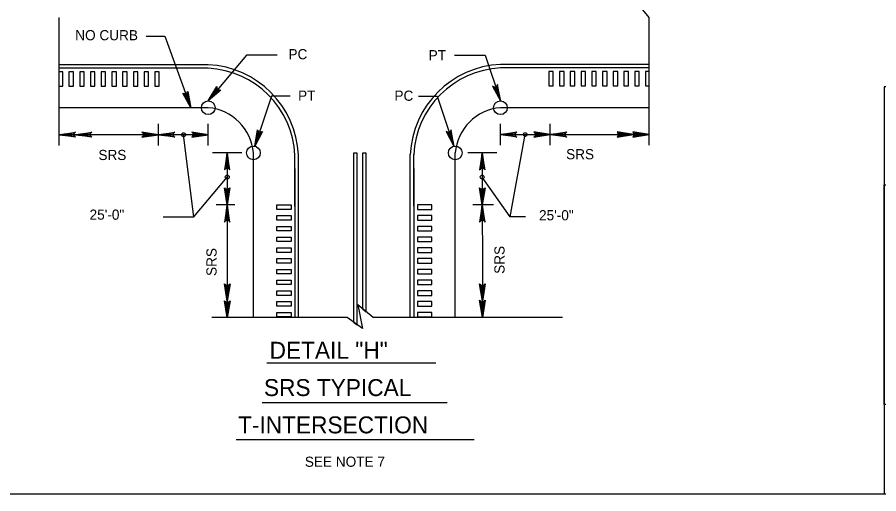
# Model space of a CAD drawing. Extents: x 632008 to 634206, y 294231 to 297795.
# Drawn here: x 632378.2 to 632632.3, y 296621.6 to 296762.1 of the extents above; entities that cross this region are included whole.
import ezdxf

# ---------------------------------------------------------------- set-up
doc = ezdxf.new("R2010")
doc.units = 0
for name, color, linetype in [('1', 7, 'Continuous'), ('3', 7, 'Continuous'), ('Level 2', 7, 'Continuous')]:
    doc.layers.add(name, color=color, linetype=linetype)

msp = doc.modelspace()

# ---------------------------------------------------------------- linework, layer by layer
at = {"layer": '1'}
for p, q in [((632451.78, 296660.25), (632501.65, 296660.25)), ((632450.44, 296648.57), (632504.99, 296648.57)), ((632442.7, 296637.57), (632512.92, 296637.57))]:
    msp.add_line(p, q, dxfattribs=at)
msp.add_lwpolyline([(632833.86, 296621.62), (632833.86, 297185.62), (632047.86, 297185.62), (632047.86, 296621.62), (632833.86, 296621.62), (632833.86, 296647.98), (632633.86, 296647.98), (632633.86, 296712.66), (632833.86, 296712.66), (632833.86, 296741.62), (632633.86, 296741.62), (632633.86, 296621.62), (632712.66, 296621.62), (632712.66, 296647.98), (632712.66, 296621.62), (632789.66, 296621.62), (632789.66, 296647.98), (632789.66, 296635.66), (632833.86, 296635.66)], dxfattribs=at)
for points in [[(632478.41, 296671.46), (632478.41, 296722.02), (632477.36, 296722.02), (632477.36, 296672.24)], [(632481.05, 296675.29), (632481.05, 296722.02), (632480, 296722.02), (632480, 296676.15)]]:
    msp.add_lwpolyline(points, close=True, dxfattribs=at)
at = {"layer": '3'}
for points in [[(632458.65, 296738.86), (632453.18, 296738.86), (632448.22, 296724.09)], [(632496.54, 296738.86), (632502, 296738.86), (632506.97, 296724.09)], [(632450.23, 296728.27), (632449.86, 296728.21), (632448.22, 296724.09), (632450.23, 296728.27), (632450.5, 296728.43), (632448.22, 296724.09), (632449.42, 296728.36), (632449.16, 296728.61), (632448.22, 296724.09), (632449.03, 296728.92), (632449.16, 296728.61)], [(632504.95, 296728.27), (632505.32, 296728.21), (632506.97, 296724.09), (632504.95, 296728.27), (632504.69, 296728.43), (632506.97, 296724.09), (632505.76, 296728.36), (632506.02, 296728.61), (632506.97, 296724.09), (632506.15, 296728.92), (632506.02, 296728.61)]]:
    msp.add_lwpolyline(points, dxfattribs=at)
for centre in [(632447.83, 296722.1), (632507.36, 296722.1)]:
    msp.add_circle(centre, 2.03, dxfattribs=at)
at = {"layer": 'Level 2'}
for p, q in [((632564.54, 296762.01), (632561.33, 296765.96)), ((632390.51, 296724.3), (632390.51, 296762.01)), ((632564.54, 296724.34), (632564.54, 296762.01)), ((632434.51, 296748.07), (632390.51, 296748.07)), ((632564.54, 296748.16), (632520.69, 296748.16)), ((632564.54, 296747.15), (632520.69, 296747.15)), ((632434.51, 296747.05), (632390.51, 296747.05)), ((632434.51, 296735.42), (632390.65, 296735.42)), ((632564.54, 296735.42), (632520.67, 296735.42)), ((632419.79, 296724.3), (632419.79, 296730.65)), ((632434.51, 296724.3), (632434.51, 296730.65)), ((632520.67, 296724.34), (632520.67, 296730.69)), ((632535.4, 296724.34), (632535.4, 296730.69)), ((632434.51, 296727.47), (632390.51, 296727.47)), ((632520.67, 296727.51), (632564.54, 296727.51)), ((632444.41, 296722.1), (632435.81, 296722.1)), ((632440.11, 296722.1), (632440.11, 296673.62)), ((632447.83, 296673.62), (632447.83, 296722.1)), ((632507.36, 296673.62), (632507.36, 296722.1)), ((632519.66, 296722.1), (632511.05, 296722.1)), ((632515.35, 296722.1), (632515.36, 296673.62)), ((632460.03, 296706.43), (632460.03, 296721.49)), ((632461.09, 296673.62), (632461.09, 296721.59)), ((632461.09, 296706.43), (632461.09, 296721.49)), ((632494.11, 296673.62), (632494.11, 296721.59)), ((632495.17, 296706.43), (632495.17, 296721.59)), ((632460.03, 296717.47), (632460.03, 296673.62)), ((632495.17, 296717.47), (632495.17, 296673.62)), ((632442.36, 296706.76), (632436.81, 296706.76)), ((632518.66, 296706.76), (632512.59, 296706.76)), ((632483.11, 296673.62), (632478.61, 296677.27)), ((632478.61, 296677.27), (632479.96, 296670.3)), ((632475.53, 296673.62), (632435.58, 296673.62)), ((632479.96, 296670.3), (632475.53, 296673.62)), ((632520.99, 296673.62), (632483.11, 296673.62)), ((632539.02, 296673.62), (632495.17, 296673.62))]:
    msp.add_line(p, q, dxfattribs=at)
for points in [[(632416.18, 296756.53), (632421.7, 296756.53), (632429.38, 296735.42)], [(632454.88, 296750.9), (632445.84, 296750.9), (632434.51, 296737.44)], [(632507.13, 296750.86), (632516.16, 296750.86), (632520.67, 296737.44)], [(632390.51, 296741.76), (632391.57, 296741.76), (632391.57, 296745.98), (632390.51, 296745.98)], [(632564.54, 296746.07), (632563.48, 296746.07), (632563.48, 296741.85), (632564.54, 296741.85)], [(632518.66, 296741.62), (632519.03, 296741.57), (632520.67, 296737.44), (632518.66, 296741.62), (632518.39, 296741.78), (632520.67, 296737.44), (632519.47, 296741.71), (632519.73, 296741.97), (632520.67, 296737.44), (632519.86, 296742.27), (632519.73, 296741.97)], [(632428.34, 296739.94), (632428.09, 296739.67), (632429.38, 296735.42), (632428.34, 296739.94), (632428.45, 296740.23), (632429.38, 296735.42), (632427.66, 296739.5), (632427.29, 296739.54), (632429.38, 296735.42), (632427, 296739.7), (632427.29, 296739.54)], [(632437.93, 296740.58), (632437.56, 296740.67), (632434.51, 296737.44), (632437.93, 296740.58), (632438.23, 296740.63), (632434.51, 296737.44), (632437.2, 296740.96), (632437.06, 296741.3), (632434.51, 296737.44), (632437.05, 296741.63), (632437.06, 296741.3)], [(632395.11, 296726.9), (632394.95, 296727.23), (632390.51, 296727.47), (632395.11, 296726.9), (632395.35, 296726.69), (632390.51, 296727.47), (632394.94, 296727.69), (632395.1, 296728.02), (632390.51, 296727.47), (632395.35, 296728.24), (632395.1, 296728.02)], [(632399.93, 296726.9), (632399.77, 296727.23), (632395.33, 296727.47), (632399.93, 296726.9), (632400.17, 296726.69), (632395.33, 296727.47), (632399.76, 296727.69), (632399.92, 296728.02), (632395.33, 296727.47), (632400.17, 296728.24), (632399.92, 296728.02)], [(632415.19, 296726.9), (632415.35, 296727.23), (632419.79, 296727.47), (632415.19, 296726.9), (632414.95, 296726.69), (632419.79, 296727.47), (632415.36, 296727.69), (632415.2, 296728.02), (632419.79, 296727.47), (632414.95, 296728.24), (632415.2, 296728.02)], [(632424.39, 296726.9), (632424.22, 296727.23), (632419.79, 296727.47), (632424.39, 296726.9), (632424.63, 296726.69), (632419.79, 296727.47), (632424.22, 296727.69), (632424.38, 296728.02), (632419.79, 296727.47), (632424.63, 296728.24), (632424.38, 296728.02)], [(632421.26, 296703.28), (632430.3, 296703.28), (632427.24, 296727.47)], [(632429.91, 296726.9), (632430.08, 296727.23), (632434.51, 296727.47), (632429.91, 296726.9), (632429.67, 296726.69), (632434.51, 296727.47), (632430.08, 296727.69), (632429.92, 296728.02), (632434.51, 296727.47), (632429.67, 296728.24), (632429.92, 296728.02)], [(632525.27, 296726.94), (632525.11, 296727.27), (632520.67, 296727.51), (632525.27, 296726.94), (632525.51, 296726.73), (632520.67, 296727.51), (632525.1, 296727.73), (632525.26, 296728.06), (632520.67, 296727.51), (632525.51, 296728.28), (632525.26, 296728.06)], [(632528.12, 296703.28), (632523.52, 296703.28), (632528.01, 296727.5)], [(632530.8, 296726.94), (632530.96, 296727.27), (632535.4, 296727.51), (632530.8, 296726.94), (632530.56, 296726.73), (632535.4, 296727.51), (632530.97, 296727.73), (632530.81, 296728.06), (632535.4, 296727.51), (632530.56, 296728.28), (632530.81, 296728.06)], [(632540, 296726.94), (632539.83, 296727.27), (632535.4, 296727.51), (632540, 296726.94), (632540.24, 296726.73), (632535.4, 296727.51), (632539.83, 296727.73), (632539.99, 296728.06), (632535.4, 296727.51), (632540.24, 296728.28), (632539.99, 296728.06)], [(632555.33, 296726.94), (632555.5, 296727.27), (632559.93, 296727.51), (632555.33, 296726.94), (632555.09, 296726.73), (632559.93, 296727.51), (632555.5, 296727.73), (632555.34, 296728.06), (632559.93, 296727.51), (632555.09, 296728.28), (632555.34, 296728.06)], [(632559.94, 296726.94), (632560.11, 296727.27), (632564.55, 296727.51), (632559.94, 296726.94), (632559.71, 296726.73), (632564.55, 296727.51), (632560.12, 296727.73), (632559.96, 296728.06), (632564.55, 296727.51), (632559.71, 296728.28), (632559.96, 296728.06)], [(632440.71, 296717.31), (632440.37, 296717.48), (632440.11, 296722.1), (632440.71, 296717.31), (632440.92, 296717.06), (632440.11, 296722.1), (632439.88, 296717.49), (632439.54, 296717.32), (632440.11, 296722.1), (632439.31, 296717.06), (632439.54, 296717.32)], [(632515.96, 296717.31), (632515.61, 296717.48), (632515.35, 296722.1), (632515.96, 296717.31), (632516.16, 296717.06), (632515.35, 296722.1), (632515.12, 296717.49), (632514.78, 296717.32), (632515.35, 296722.1), (632514.55, 296717.06), (632514.78, 296717.32)], [(632421.26, 296703.28), (632430.3, 296703.28), (632440.13, 296714.93)], [(632528.12, 296703.28), (632523.52, 296703.28), (632515.31, 296714.93)], [(632440.71, 296711.56), (632440.37, 296711.38), (632440.11, 296706.76), (632440.71, 296711.56), (632440.92, 296711.8), (632440.11, 296706.76), (632439.88, 296711.37), (632439.54, 296711.54), (632440.11, 296706.76), (632439.31, 296711.8), (632439.54, 296711.54)], [(632515.96, 296711.56), (632515.61, 296711.38), (632515.35, 296706.76), (632515.96, 296711.56), (632516.16, 296711.8), (632515.35, 296706.76), (632515.12, 296711.37), (632514.78, 296711.54), (632515.35, 296706.76), (632514.55, 296711.8), (632514.78, 296711.54)], [(632440.71, 296701.97), (632440.37, 296702.14), (632440.11, 296706.76), (632440.71, 296701.97), (632440.92, 296701.72), (632440.11, 296706.76), (632439.88, 296702.15), (632439.54, 296701.98), (632440.11, 296706.76), (632439.31, 296701.72), (632439.54, 296701.98)], [(632515.96, 296701.97), (632515.61, 296702.14), (632515.35, 296706.76), (632515.96, 296701.97), (632516.16, 296701.72), (632515.35, 296706.76), (632515.12, 296702.15), (632514.78, 296701.98), (632515.35, 296706.76), (632514.55, 296701.72), (632514.78, 296701.98)], [(632440.72, 296683.22), (632440.37, 296683.05), (632440.12, 296678.43), (632440.72, 296683.22), (632440.93, 296683.47), (632440.12, 296678.43), (632439.89, 296683.04), (632439.55, 296683.21), (632440.12, 296678.43), (632439.32, 296683.47), (632439.55, 296683.21)], [(632515.96, 296683.22), (632515.61, 296683.05), (632515.36, 296678.43), (632515.96, 296683.22), (632516.17, 296683.47), (632515.36, 296678.43), (632515.13, 296683.04), (632514.79, 296683.21), (632515.36, 296678.43), (632514.56, 296683.47), (632514.79, 296683.21)], [(632515.96, 296678.42), (632515.61, 296678.24), (632515.36, 296673.62), (632515.96, 296678.42), (632516.17, 296678.66), (632515.36, 296673.62), (632515.13, 296678.23), (632514.79, 296678.4), (632515.36, 296673.62), (632514.56, 296678.66), (632514.79, 296678.4)], [(632440.72, 296678.21), (632440.37, 296678.05), (632440.12, 296673.62), (632440.72, 296678.21), (632440.93, 296678.45), (632440.12, 296673.62), (632439.89, 296678.04), (632439.55, 296678.2), (632440.12, 296673.62), (632439.32, 296678.45), (632439.55, 296678.2)]]:
    msp.add_lwpolyline(points, dxfattribs=at)
for points in [[(632393.42, 296741.76), (632394.74, 296741.76), (632394.74, 296745.98), (632393.42, 296745.98)], [(632396.59, 296741.76), (632397.91, 296741.76), (632397.91, 296745.98), (632396.59, 296745.98)], [(632399.75, 296741.76), (632401.07, 296741.76), (632401.07, 296745.98), (632399.75, 296745.98)], [(632402.92, 296741.76), (632404.24, 296741.76), (632404.24, 296745.98), (632402.92, 296745.98)], [(632406.09, 296741.76), (632407.41, 296741.76), (632407.41, 296745.98), (632406.09, 296745.98)], [(632409.25, 296741.76), (632410.57, 296741.76), (632410.57, 296745.98), (632409.25, 296745.98)], [(632412.42, 296741.76), (632413.74, 296741.76), (632413.74, 296745.98), (632412.42, 296745.98)], [(632415.59, 296741.76), (632416.91, 296741.76), (632416.91, 296745.98), (632415.59, 296745.98)], [(632418.75, 296741.76), (632420.07, 296741.76), (632420.07, 296745.98), (632418.75, 296745.98)], [(632534.97, 296741.85), (632536.29, 296741.85), (632536.29, 296746.07), (632534.97, 296746.07)], [(632538.14, 296741.85), (632539.46, 296741.85), (632539.46, 296746.07), (632538.14, 296746.07)], [(632541.31, 296741.85), (632542.63, 296741.85), (632542.63, 296746.07), (632541.31, 296746.07)], [(632544.48, 296741.85), (632545.8, 296741.85), (632545.8, 296746.07), (632544.48, 296746.07)], [(632547.64, 296741.85), (632548.96, 296741.85), (632548.96, 296746.07), (632547.64, 296746.07)], [(632550.81, 296741.85), (632552.13, 296741.85), (632552.13, 296746.07), (632550.81, 296746.07)], [(632553.98, 296741.85), (632555.3, 296741.85), (632555.3, 296746.07), (632553.98, 296746.07)], [(632557.14, 296741.85), (632558.46, 296741.85), (632558.46, 296746.07), (632557.14, 296746.07)], [(632560.31, 296741.85), (632561.63, 296741.85), (632561.63, 296746.07), (632560.31, 296746.07)], [(632454.74, 296705.44), (632454.74, 296706.76), (632458.96, 296706.76), (632458.96, 296705.44)], [(632500.46, 296705.44), (632500.46, 296706.76), (632496.24, 296706.76), (632496.24, 296705.44)], [(632454.74, 296702.28), (632454.74, 296703.6), (632458.96, 296703.6), (632458.96, 296702.28)], [(632500.46, 296702.28), (632500.46, 296703.6), (632496.24, 296703.6), (632496.24, 296702.28)], [(632454.74, 296699.11), (632454.74, 296700.43), (632458.96, 296700.43), (632458.96, 296699.11)], [(632500.46, 296699.11), (632500.46, 296700.43), (632496.24, 296700.43), (632496.24, 296699.11)], [(632454.74, 296695.94), (632454.74, 296697.26), (632458.96, 296697.26), (632458.96, 296695.94)], [(632500.46, 296695.94), (632500.46, 296697.26), (632496.24, 296697.26), (632496.24, 296695.94)], [(632454.74, 296692.77), (632454.74, 296694.09), (632458.96, 296694.09), (632458.96, 296692.77)], [(632500.46, 296692.77), (632500.46, 296694.09), (632496.24, 296694.09), (632496.24, 296692.77)], [(632454.74, 296689.61), (632454.74, 296690.93), (632458.96, 296690.93), (632458.96, 296689.61)], [(632500.46, 296689.61), (632500.46, 296690.93), (632496.24, 296690.93), (632496.24, 296689.61)], [(632454.74, 296686.44), (632454.74, 296687.76), (632458.96, 296687.76), (632458.96, 296686.44)], [(632500.46, 296686.44), (632500.46, 296687.76), (632496.24, 296687.76), (632496.24, 296686.44)], [(632454.74, 296683.27), (632454.74, 296684.59), (632458.96, 296684.59), (632458.96, 296683.27)], [(632500.46, 296683.27), (632500.46, 296684.59), (632496.24, 296684.59), (632496.24, 296683.27)], [(632454.74, 296680.11), (632454.74, 296681.43), (632458.96, 296681.43), (632458.96, 296680.11)], [(632500.46, 296680.11), (632500.46, 296681.43), (632496.24, 296681.43), (632496.24, 296680.11)], [(632454.74, 296676.94), (632454.74, 296678.26), (632458.96, 296678.26), (632458.96, 296676.94)], [(632500.46, 296676.94), (632500.46, 296678.26), (632496.24, 296678.26), (632496.24, 296676.94)], [(632454.74, 296673.77), (632454.74, 296675.09), (632458.96, 296675.09), (632458.96, 296673.77)], [(632500.46, 296673.77), (632500.46, 296675.09), (632496.24, 296675.09), (632496.24, 296673.77)]]:
    msp.add_lwpolyline(points, close=True, dxfattribs=at)
for centre, radius in [((632434.51, 296735.42), 2.03), ((632520.67, 296735.42), 2.03), ((632427.24, 296727.47), 0.558), ((632528.01, 296727.5), 0.558), ((632440.12, 296714.97), 0.581), ((632515.3, 296714.97), 0.581)]:
    msp.add_circle(centre, radius, dxfattribs=at)
for centre, radius, start, end in [((632433.23, 296720.21), 27.91, 2.6354, 87.3646), ((632521.97, 296720.3), 27.91, 92.6354, 177.3646), ((632521.97, 296720.3), 26.86, 92.6354, 177.3646), ((632433.23, 296720.21), 26.86, 2.6354, 87.3646), ((632433.28, 296720.87), 14.6, 4.837, 85.163), ((632521.9, 296720.87), 14.6, 94.837, 175.163)]:
    msp.add_arc(centre, radius, start, end, dxfattribs=at)

# ---------------------------------------------------------------- texts
at = {"layer": '3'}
for s, p in [('PT', (632461.01, 296737.46)), ('PC', (632489.43, 296737.46))]:
    msp.add_text(s, height=3, dxfattribs=at).set_placement(p)
at = {"layer": 'Level 2'}
for s, height, p in [('NO CURB', 3, (632395.28, 296755.3)), ('PC', 3, (632458.17, 296749.7)), ('PT', 3, (632499.52, 296749.4)), ('SRS', 3, (632402.11, 296719.99)), ('SRS', 3, (632540.06, 296720.22)), ('25\'-0"', 3, (632399.51, 296702.4)), ('25\'-0"', 3, (632532.08, 296702.22)), ('DETAIL "H"', 5, (632452.61, 296661.42)), ('SRS TYPICAL', 5, (632450.94, 296650.42)), ('T-INTERSECTION', 5, (632443.3, 296639.42)), ('SEE NOTE 7', 3, (632463, 296629.57))]:
    msp.add_text(s, height=height, dxfattribs=at).set_placement(p)
for p in [(632436.96, 296685.82), (632521.9, 296686.44)]:
    msp.add_text('SRS', height=3, rotation=90, dxfattribs=at).set_placement(p)

doc.saveas('drawing.dxf')
